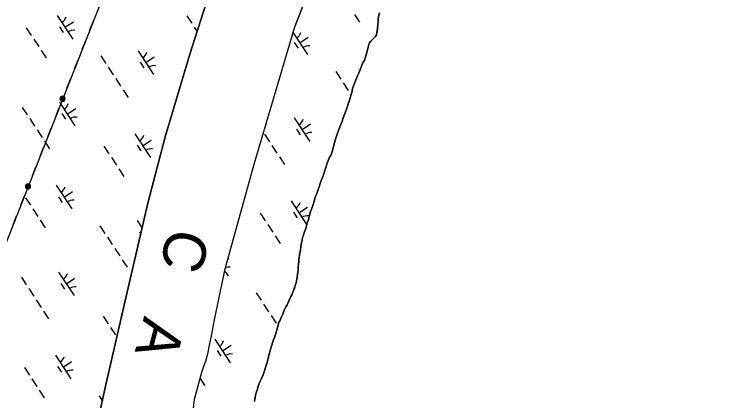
# Model space of a CAD drawing. Extents: x 3945642 to 3966284, y 206476 to 228921.
# Drawn here: x 3957545 to 3958793, y 219115 to 219801 of the extents above; entities that cross this region are included whole.
import ezdxf

# ---------------------------------------------------------------- set-up
doc = ezdxf.new("R2010")
doc.units = 0
for name, color, linetype in [('V-RIVR-IDEN', 7, 'Continuous'), ('V-TOPO-SHOR', 7, 'Continuous'), ('V-UTIL-LINE', 7, 'Continuous'), ('V-WETL-SWMP', 7, 'Continuous')]:
    doc.layers.add(name, color=color, linetype=linetype)

msp = doc.modelspace()

# ---------------------------------------------------------------- linework, layer by layer
at = {"layer": 'V-TOPO-SHOR'}
for points in [[(3957862.7, 219102.6), (3957864.7, 219118.7), (3957877.5, 219166.5), (3957881.2, 219177), (3957884.5, 219186.1), (3957888.1, 219198.6), (3957891.4, 219214.1), (3957894.9, 219230.9), (3957899.8, 219259.1), (3957918.9, 219349.8), (3957970.1, 219534.8), (3958042.5, 219778.5), (3958134.5, 220016.7)], [(3957674.6, 218994.5), (3957706.8, 219141.4), (3957743, 219298.2), (3957782.2, 219465.8), (3957812.9, 219583.2), (3957856.5, 219729.8), (3957885.2, 219820.3)], [(3958171.9, 219742), (3958172.8, 219745.1), (3958174.6, 219749.8), (3958176.5, 219753.2), (3958180.7, 219757.2), (3958184.5, 219760.4), (3958186.6, 219764.1), (3958187.4, 219767.8), (3958188.5, 219775.4), (3958189.3, 219783.1), (3958189.7, 219786.4), (3958189.9, 219791.3), (3958190.6, 219796.7), (3958192.1, 219803.2)], [(3958010.3, 219241.7), (3958011.3, 219244.9), (3958012.7, 219250.4), (3958014, 219254.4), (3958015.4, 219257.5), (3958017.9, 219263.5), (3958020.8, 219269.4), (3958023.5, 219276), (3958024.8, 219278.9), (3958026.8, 219282.8), (3958028.4, 219285.6), (3958030.4, 219289.7), (3958032.3, 219294), (3958033.6, 219297.1), (3958035.1, 219300.3), (3958036.8, 219303.3), (3958038.8, 219308), (3958040, 219311), (3958041.8, 219315.5), (3958043.1, 219320), (3958044, 219323), (3958044.9, 219327.7), (3958046.5, 219335.5), (3958047.1, 219339.2), (3958047.6, 219343.8), (3958047.9, 219347.3), (3958048.4, 219352.7), (3958048.9, 219358.5), (3958049.2, 219362.3), (3958049.5, 219366), (3958049.8, 219369.2), (3958050.7, 219373.8), (3958051.2, 219377.3), (3958052.1, 219382.5), (3958052.9, 219388.3), (3958053.6, 219392.7), (3958055, 219400.3), (3958055.7, 219404.8), (3958056.9, 219407.7), (3958059, 219413.4), (3958061.5, 219421.3), (3958062.6, 219425.1), (3958064.3, 219431.1), (3958065.7, 219435.4), (3958067.5, 219441.8), (3958068.8, 219446.3), (3958070.8, 219452.9), (3958072.2, 219456.5), (3958074.4, 219463.3), (3958076.6, 219469.6), (3958079.1, 219477.6), (3958080.3, 219481.2), (3958082.1, 219486.6), (3958083.4, 219490), (3958085.2, 219494.9), (3958086.8, 219500.5), (3958088.3, 219504.2), (3958090.7, 219510.1), (3958092.4, 219514.5), (3958095, 219522), (3958096.6, 219527.6), (3958099.6, 219536.6), (3958101.7, 219542.4), (3958104.2, 219548.3), (3958106.3, 219551.4), (3958108.1, 219557.2), (3958109, 219560.1), (3958110, 219564.2), (3958111.9, 219570.6), (3958113.3, 219575.7), (3958115.5, 219582.9), (3958116.9, 219587.9), (3958119.3, 219594.6), (3958121.9, 219600.9), (3958123.5, 219605.3), (3958125.8, 219611.5), (3958127.2, 219615.6), (3958129.8, 219621.7), (3958131.6, 219626), (3958133.7, 219632.7), (3958135.3, 219637.5), (3958136.9, 219642.1), (3958139.1, 219648.7), (3958140.4, 219652.4), (3958141.8, 219658.5), (3958142.9, 219662.3), (3958144.4, 219668.3), (3958145.5, 219672.3), (3958147.8, 219678.5), (3958149.5, 219682.9), (3958152.4, 219689.6), (3958155.3, 219697), (3958157.8, 219702.3), (3958161, 219710.4), (3958163.3, 219715.8), (3958165.3, 219719.6), (3958166.7, 219722.8), (3958168.6, 219728.6), (3958169.7, 219732.7), (3958171.1, 219738.4), (3958171.9, 219742)], [(3957970.6, 219114.3), (3957971.2, 219118.5), (3957972.7, 219125), (3957973.9, 219129.6), (3957975.9, 219136.5), (3957977.5, 219141.4), (3957980.5, 219149), (3957982.9, 219154), (3957986.1, 219161.9), (3957987.9, 219167), (3957990.3, 219174.5), (3957992.4, 219181.7), (3957993.7, 219186.4), (3957995.6, 219192.9), (3957996.3, 219196.8), (3957997.4, 219200.6), (3957998.3, 219204.2), (3957999.7, 219209.3), (3958001.3, 219214.4), (3958002.7, 219218.4), (3958004.7, 219223.9), (3958006.1, 219227.7), (3958007.9, 219233.3), (3958008.9, 219236.8), (3958010.3, 219241.7)]]:
    msp.add_lwpolyline(points, dxfattribs=at)
at = {"layer": 'V-UTIL-LINE'}
for points in [[(3958881.3, 222827.3), (3957109.9, 218327), (3961480.2, 211741.6)], [(3957685, 219788.2), (3957678.8, 219772.4)], [(3957671.5, 219753.8), (3957665.3, 219738)], [(3957657.9, 219719.4), (3957651.7, 219703.5)], [(3957644.4, 219684.9), (3957638.2, 219669.1)], [(3957631, 219651), (3957632.4, 219651.3), (3957631.6, 219652.1), (3957630.2, 219651.7), (3957629.9, 219650.3), (3957631.4, 219649.6), (3957633.6, 219650.5), (3957633.5, 219652.6), (3957631.5, 219654.1), (3957629.4, 219653.3), (3957628.1, 219651.4), (3957628.9, 219649.1), (3957631.4, 219648), (3957635.2, 219649.3), (3957635.5, 219651.1), (3957635.2, 219652.8), (3957634.2, 219654.2), (3957632.7, 219655.2), (3957631, 219655.5), (3957629.2, 219655.1), (3957627.8, 219654.1), (3957626.8, 219652.6), (3957626.5, 219650.9), (3957626.9, 219649.2), (3957627.9, 219647.7), (3957629.4, 219646.8), (3957631.1, 219646.5), (3957632.8, 219646.9), (3957634.3, 219647.9), (3957635.2, 219649.3)], [(3957623.9, 219632.8), (3957617.7, 219617)], [(3957610.3, 219598.4), (3957604.1, 219582.6)], [(3957596.8, 219564), (3957590.6, 219548.1)], [(3957583.2, 219529.5), (3957577, 219513.7)], [(3957569.9, 219495.6), (3957571.3, 219495.9), (3957570.4, 219496.7), (3957569.1, 219496.3), (3957568.7, 219494.9), (3957570.2, 219494.2), (3957572.4, 219495.1), (3957572.3, 219497.2), (3957570.3, 219498.7), (3957568.2, 219497.9), (3957567, 219496), (3957567.7, 219493.8), (3957570.2, 219492.6), (3957574.1, 219493.9), (3957574.4, 219495.7), (3957574, 219497.4), (3957573, 219498.8), (3957571.5, 219499.8), (3957569.8, 219500.1), (3957568.1, 219499.7), (3957566.6, 219498.7), (3957565.7, 219497.2), (3957565.4, 219495.5), (3957565.7, 219493.8), (3957566.7, 219492.3), (3957568.2, 219491.4), (3957569.9, 219491.1), (3957571.7, 219491.5), (3957573.1, 219492.5), (3957574.1, 219493.9)], [(3957562.7, 219477.4), (3957556.5, 219461.6)], [(3957549.2, 219443), (3957542.9, 219427.2)]]:
    msp.add_lwpolyline(points, dxfattribs=at)
at = {"layer": 'V-WETL-SWMP'}
for p, q in [((3958042.5, 219778.5), (3958134.5, 220016.6)), ((3957621.6, 219798.6), (3957649, 219756.7)), ((3957851.1, 219798), (3957859.9, 219784.6)), ((3958148.1, 219800.1), (3958156.9, 219786.7)), ((3958190.6, 219796.7), (3958189.9, 219791.3)), ((3958192.1, 219803.2), (3958190.6, 219796.7)), ((3957635.3, 219777.6), (3957650.3, 219787.5)), ((3958189.3, 219783.1), (3958188.5, 219775.4)), ((3958189.7, 219786.4), (3958189.3, 219783.1)), ((3958189.9, 219791.3), (3958189.7, 219786.4)), ((3957566.9, 219776.7), (3957575.6, 219763.3)), ((3957625.5, 219778.4), (3957632.1, 219768.4)), ((3957864.3, 219777.9), (3957869.3, 219770.2)), ((3957970.1, 219534.8), (3958042.5, 219778.5)), ((3958039.3, 219767.9), (3958064.8, 219729.1)), ((3958187.4, 219767.8), (3958186.6, 219764.1)), ((3958188.5, 219775.4), (3958187.4, 219767.8)), ((3957580, 219756.6), (3957588.8, 219743.3)), ((3958051.1, 219750), (3958066.1, 219759.9)), ((3958180.7, 219757.2), (3958176.5, 219753.2)), ((3958184.5, 219760.4), (3958180.7, 219757.2)), ((3958186.6, 219764.1), (3958184.5, 219760.4)), ((3958041.3, 219750.8), (3958047.9, 219740.8)), ((3958172.8, 219745.1), (3958171.9, 219742)), ((3958174.6, 219749.8), (3958172.8, 219745.1)), ((3958176.5, 219753.2), (3958174.6, 219749.8)), ((3957593.2, 219736.6), (3957601.9, 219723.2)), ((3957764.6, 219736), (3957792, 219694.2)), ((3958169.7, 219732.7), (3958168.6, 219728.6)), ((3958171.1, 219738.4), (3958169.7, 219732.7)), ((3958171.9, 219742), (3958171.1, 219738.4)), ((3957698.8, 219726.9), (3957707.6, 219713.5)), ((3957778.3, 219715.1), (3957793.4, 219725)), ((3958165.3, 219719.6), (3958163.3, 219715.8)), ((3958166.7, 219722.8), (3958165.3, 219719.6)), ((3958168.6, 219728.6), (3958166.7, 219722.8)), ((3957712, 219706.8), (3957720.8, 219693.4)), ((3957768.6, 219715.9), (3957775.2, 219705.9)), ((3958161, 219710.4), (3958157.8, 219702.3)), ((3958163.3, 219715.8), (3958161, 219710.4)), ((3958114.6, 219699.3), (3958123.4, 219685.9)), ((3958155.3, 219697), (3958152.4, 219689.6)), ((3958157.8, 219702.3), (3958155.3, 219697)), ((3957725.1, 219686.7), (3957733.9, 219673.4)), ((3958149.5, 219682.9), (3958147.8, 219678.5)), ((3958152.4, 219689.6), (3958149.5, 219682.9)), ((3958127.8, 219679.2), (3958136.6, 219665.8)), ((3958144.4, 219668.3), (3958142.9, 219662.3)), ((3958145.5, 219672.3), (3958144.4, 219668.3)), ((3958147.8, 219678.5), (3958145.5, 219672.3)), ((3957738.3, 219666.7), (3957747.1, 219653.3)), ((3958141.8, 219658.5), (3958140.4, 219652.4)), ((3958140.9, 219659.1), (3958141.7, 219658)), ((3958142.9, 219662.3), (3958141.8, 219658.5)), ((3957625.5, 219644.9), (3957652.9, 219603)), ((3958139.1, 219648.7), (3958136.9, 219642.1)), ((3958140.4, 219652.4), (3958139.1, 219648.7)), ((3957559.7, 219635.7), (3957568.5, 219622.4)), ((3957639.2, 219623.9), (3957654.3, 219633.8)), ((3958133.7, 219632.7), (3958131.6, 219626)), ((3958135.3, 219637.5), (3958133.7, 219632.7)), ((3958136.9, 219642.1), (3958135.3, 219637.5)), ((3957629.5, 219624.7), (3957636, 219614.7)), ((3958129.8, 219621.7), (3958127.2, 219615.6)), ((3958131.6, 219626), (3958129.8, 219621.7)), ((3957572.9, 219615.7), (3957581.6, 219602.3)), ((3958041.3, 219617.2), (3958068.7, 219575.4)), ((3958055, 219596.3), (3958070.1, 219606.2)), ((3958125.8, 219611.5), (3958123.5, 219605.3)), ((3958127.2, 219615.6), (3958125.8, 219611.5)), ((3957586, 219595.6), (3957594.8, 219582.2)), ((3958045.3, 219597.1), (3958051.8, 219587.1)), ((3958119.3, 219594.6), (3958116.9, 219587.9)), ((3958121.9, 219600.9), (3958119.3, 219594.6)), ((3958123.5, 219605.3), (3958121.9, 219600.9)), ((3957759.1, 219588.6), (3957786.5, 219546.8)), ((3957988.7, 219588), (3957997.4, 219574.7)), ((3958115.5, 219582.9), (3958113.3, 219575.7)), ((3958116.9, 219587.9), (3958115.5, 219582.9)), ((3957599.2, 219575.5), (3957607.9, 219562.1)), ((3957763, 219568.5), (3957769.6, 219558.5)), ((3957772.8, 219567.7), (3957787.8, 219577.6)), ((3958001.8, 219568), (3958010.6, 219554.6)), ((3958111.9, 219570.6), (3958110, 219564.2)), ((3958113.3, 219575.7), (3958111.9, 219570.6)), ((3957704.4, 219566.8), (3957713.2, 219553.4)), ((3958108.1, 219557.2), (3958106.3, 219551.4)), ((3958109, 219560.1), (3958108.1, 219557.2)), ((3958110, 219564.2), (3958109, 219560.1)), ((3957717.5, 219546.7), (3957726.3, 219533.3)), ((3958015, 219547.9), (3958023.7, 219534.5)), ((3958104.2, 219548.3), (3958101.7, 219542.4)), ((3958106.3, 219551.4), (3958104.2, 219548.3)), ((3957918.9, 219349.8), (3957970.1, 219534.8)), ((3958099.6, 219536.6), (3958096.6, 219527.6)), ((3958101.7, 219542.4), (3958099.6, 219536.6)), ((3957730.7, 219526.6), (3957739.5, 219513.3)), ((3958095, 219522), (3958092.4, 219514.5)), ((3958096.6, 219527.6), (3958095, 219522)), ((3958090.7, 219510.1), (3958088.3, 219504.2)), ((3958092.4, 219514.5), (3958090.7, 219510.1)), ((3957619.9, 219497.5), (3957647.3, 219455.7)), ((3958085.2, 219494.9), (3958083.4, 219490)), ((3958086.8, 219500.5), (3958085.2, 219494.9)), ((3958088.3, 219504.2), (3958086.8, 219500.5)), ((3957633.6, 219476.6), (3957648.7, 219486.4)), ((3958080.3, 219481.2), (3958079.1, 219477.6)), ((3958082.1, 219486.6), (3958080.3, 219481.2)), ((3958083.4, 219490), (3958082.1, 219486.6)), ((3957565.3, 219475.6), (3957574, 219462.3)), ((3957623.9, 219477.4), (3957630.5, 219467.3)), ((3958035.7, 219469.9), (3958063.1, 219428)), ((3958076.6, 219469.6), (3958074.4, 219463.3)), ((3958079.1, 219477.6), (3958076.6, 219469.6)), ((3958049.4, 219449), (3958064.5, 219458.8)), ((3958072.2, 219456.5), (3958070.8, 219452.9)), ((3958074.4, 219463.3), (3958072.2, 219456.5)), ((3957578.4, 219455.6), (3957587.2, 219442.2)), ((3957981.1, 219448), (3957989.8, 219434.6)), ((3958039.7, 219449.7), (3958046.3, 219439.7)), ((3958068.8, 219446.3), (3958067.5, 219441.8)), ((3958070.8, 219452.9), (3958068.8, 219446.3)), ((3957591.6, 219435.5), (3957600.3, 219422.1)), ((3957763, 219434.9), (3957771.8, 219421.5)), ((3958064.3, 219431.1), (3958062.6, 219425.1)), ((3958065.7, 219435.4), (3958064.3, 219431.1)), ((3958067.5, 219441.8), (3958065.7, 219435.4)), ((3957697.2, 219425.8), (3957706, 219412.4)), ((3957994.2, 219428), (3958003, 219414.6)), ((3958061.5, 219421.3), (3958059, 219413.4)), ((3958062.6, 219425.1), (3958061.5, 219421.3)), ((3957710.4, 219405.7), (3957719.1, 219392.4)), ((3957767, 219414.8), (3957769.4, 219411.1)), ((3958007.4, 219407.9), (3958016.1, 219394.5)), ((3958056.9, 219407.7), (3958055.7, 219404.8)), ((3958059, 219413.4), (3958056.9, 219407.7)), ((3958055, 219400.3), (3958053.6, 219392.7)), ((3958055.7, 219404.8), (3958055, 219400.3)), ((3957723.5, 219385.7), (3957732.3, 219372.3)), ((3958052.1, 219382.5), (3958051.2, 219377.3)), ((3958052.9, 219388.3), (3958052.1, 219382.5)), ((3958053.6, 219392.7), (3958052.9, 219388.3)), ((3958049.8, 219369.2), (3958049.5, 219366)), ((3958050.7, 219373.8), (3958049.8, 219369.2)), ((3958051.2, 219377.3), (3958050.7, 219373.8)), ((3957736.7, 219365.6), (3957745.4, 219352.2)), ((3957923.4, 219366.4), (3957925.4, 219367.7)), ((3958048.9, 219358.5), (3958048.4, 219352.7)), ((3958049.2, 219362.3), (3958048.9, 219358.5)), ((3958049.5, 219366), (3958049.2, 219362.3)), ((3957623.9, 219343.8), (3957651.3, 219302)), ((3957899.8, 219259.1), (3957918.9, 219349.8)), ((3957918, 219346), (3957924, 219336.9)), ((3958047.6, 219343.8), (3958047.1, 219339.2)), ((3958047.9, 219347.3), (3958047.6, 219343.8)), ((3958048.4, 219352.7), (3958047.9, 219347.3)), ((3957558.1, 219334.7), (3957566.9, 219321.3)), ((3957637.6, 219322.9), (3957652.6, 219332.7)), ((3958046.5, 219335.5), (3958044.9, 219327.7)), ((3958047.1, 219339.2), (3958046.5, 219335.5)), ((3957627.8, 219323.7), (3957634.4, 219313.6)), ((3958043.1, 219320), (3958041.8, 219315.5)), ((3958044, 219323), (3958043.1, 219320)), ((3958044.9, 219327.7), (3958044, 219323)), ((3957571.2, 219314.6), (3957580, 219301.2)), ((3957973.9, 219307), (3957982.7, 219293.7)), ((3958038.8, 219308), (3958036.8, 219303.3)), ((3958040, 219311), (3958038.8, 219308)), ((3958039.7, 219316.2), (3958041.2, 219313.9)), ((3958041.8, 219315.5), (3958040, 219311)), ((3957584.4, 219294.5), (3957593.2, 219281.1)), ((3958032.3, 219294), (3958030.4, 219289.7)), ((3958033.6, 219297.1), (3958032.3, 219294)), ((3958035.1, 219300.3), (3958033.6, 219297.1)), ((3958036.8, 219303.3), (3958035.1, 219300.3)), ((3957987, 219287), (3957995.8, 219273.6)), ((3958026.8, 219282.8), (3958024.8, 219278.9)), ((3958028.4, 219285.6), (3958026.8, 219282.8)), ((3958030.4, 219289.7), (3958028.4, 219285.6)), ((3957597.5, 219274.4), (3957606.3, 219261.1)), ((3958020.8, 219269.4), (3958017.9, 219263.5)), ((3958023.5, 219276), (3958020.8, 219269.4)), ((3958024.8, 219278.9), (3958023.5, 219276)), ((3957702.8, 219265.7), (3957711.5, 219252.3)), ((3957894.9, 219230.9), (3957899.8, 219259.1)), ((3958000.2, 219266.9), (3958009, 219253.5)), ((3958015.4, 219257.5), (3958014, 219254.4)), ((3958017.9, 219263.5), (3958015.4, 219257.5)), ((3957715.9, 219245.6), (3957724.7, 219232.3)), ((3958011.3, 219244.9), (3958010.3, 219241.7)), ((3958012.7, 219250.4), (3958011.3, 219244.9)), ((3958014, 219254.4), (3958012.7, 219250.4)), ((3958007.9, 219233.3), (3958006.1, 219227.7)), ((3958008.9, 219236.8), (3958007.9, 219233.3)), ((3958010.3, 219241.7), (3958008.9, 219236.8)), ((3957891.4, 219214.1), (3957894.9, 219230.9)), ((3957900.5, 219225), (3957927.9, 219183.2)), ((3958004.7, 219223.9), (3958002.7, 219218.4)), ((3958006.1, 219227.7), (3958004.7, 219223.9)), ((3957888.1, 219198.6), (3957891.4, 219214.1)), ((3957914.2, 219204.1), (3957929.3, 219214)), ((3957999.7, 219209.3), (3957998.3, 219204.2)), ((3958001.3, 219214.4), (3957999.7, 219209.3)), ((3958002.7, 219218.4), (3958001.3, 219214.4)), ((3957618.3, 219196.4), (3957645.7, 219154.6)), ((3957884.5, 219186.1), (3957888.1, 219198.6)), ((3957904.5, 219204.9), (3957911.1, 219194.9)), ((3957996.3, 219196.8), (3957995.6, 219192.9)), ((3957997.4, 219200.6), (3957996.3, 219196.8)), ((3957998.3, 219204.2), (3957997.4, 219200.6)), ((3957632, 219175.5), (3957647.1, 219185.4)), ((3957881.2, 219177), (3957884.5, 219186.1)), ((3957992.4, 219181.7), (3957990.3, 219174.5)), ((3957993.7, 219186.4), (3957992.4, 219181.7)), ((3957995.6, 219192.9), (3957993.7, 219186.4)), ((3957563.6, 219174.6), (3957572.4, 219161.2)), ((3957622.3, 219176.3), (3957628.9, 219166.3)), ((3957877.5, 219166.5), (3957881.2, 219177)), ((3957990.3, 219174.5), (3957987.9, 219167)), ((3957864.7, 219118.7), (3957877.5, 219166.5)), ((3957986.1, 219161.9), (3957982.9, 219154)), ((3957987.9, 219167), (3957986.1, 219161.9)), ((3957576.8, 219154.5), (3957585.6, 219141.1)), ((3957874.5, 219155.2), (3957883, 219142.3)), ((3957980.5, 219149), (3957977.5, 219141.4)), ((3957979.4, 219147), (3957979.6, 219146.7)), ((3957982.9, 219154), (3957980.5, 219149)), ((3957589.9, 219134.4), (3957598.7, 219121)), ((3957975.9, 219136.5), (3957973.9, 219129.6)), ((3957977.5, 219141.4), (3957975.9, 219136.5)), ((3957695.6, 219124.7), (3957701.3, 219116.1)), ((3957862.7, 219102.6), (3957864.7, 219118.7)), ((3957972.7, 219125), (3957971.2, 219118.5)), ((3957973.9, 219129.6), (3957972.7, 219125)), ((3957971.2, 219118.5), (3957970.6, 219114.3))]:
    msp.add_line(p, q, dxfattribs=at)
msp.add_lwpolyline([(3957885.2, 219820.3), (3957856.5, 219729.8), (3957812.9, 219583.2), (3957782.2, 219465.8), (3957743, 219298.2), (3957706.8, 219141.4), (3957674.6, 218994.5)], dxfattribs=at)
for centre, start, end in [((3957620.3, 219800.9), 302.4575, 344.0011), ((3957650.6, 219754.7), 82.4574, 124.0011), ((3958036.1, 219773.3), 302.4575, 344.0011), ((3958066.4, 219727), 82.4574, 124.0011), ((3957763.4, 219738.3), 302.4575, 344.0011), ((3957793.7, 219692.1), 82.4574, 124.0011), ((3957624.3, 219647.2), 302.4575, 344.0011), ((3957654.5, 219601), 82.4574, 124.0011), ((3958040.1, 219619.6), 302.4575, 344.0011), ((3957757.8, 219591), 302.4575, 344.0011), ((3958070.3, 219573.4), 82.4574, 124.0011), ((3957788.1, 219544.7), 82.4574, 124.0011), ((3957618.7, 219499.8), 302.4575, 344.0011), ((3957649, 219453.6), 82.4574, 124.0011), ((3958034.5, 219472.2), 302.4575, 344.0011), ((3958064.8, 219426), 82.4574, 124.0011), ((3957761.8, 219437.3), 302.4575, 306.2863), ((3957925.6, 219334.8), 82.4574, 111.268), ((3957622.6, 219346.1), 302.4575, 344.0011), ((3957652.9, 219299.9), 82.4574, 124.0011), ((3957899.3, 219227.3), 302.4575, 344.0011), ((3957617.1, 219198.7), 302.4575, 344.0011), ((3957929.6, 219181.1), 82.4574, 124.0011), ((3957647.4, 219152.5), 82.4574, 124.0011)]:
    msp.add_arc(centre, 17.6, start, end, dxfattribs=at)

# ---------------------------------------------------------------- texts
at = {"layer": 'V-RIVR-IDEN'}
for s, p in [('C', (3957820.5, 219425.4)), ('A', (3957775.7, 219266.9))]:
    msp.add_text(s, height=75, rotation=255.2653, dxfattribs=at).set_placement(p)

doc.saveas('drawing.dxf')
